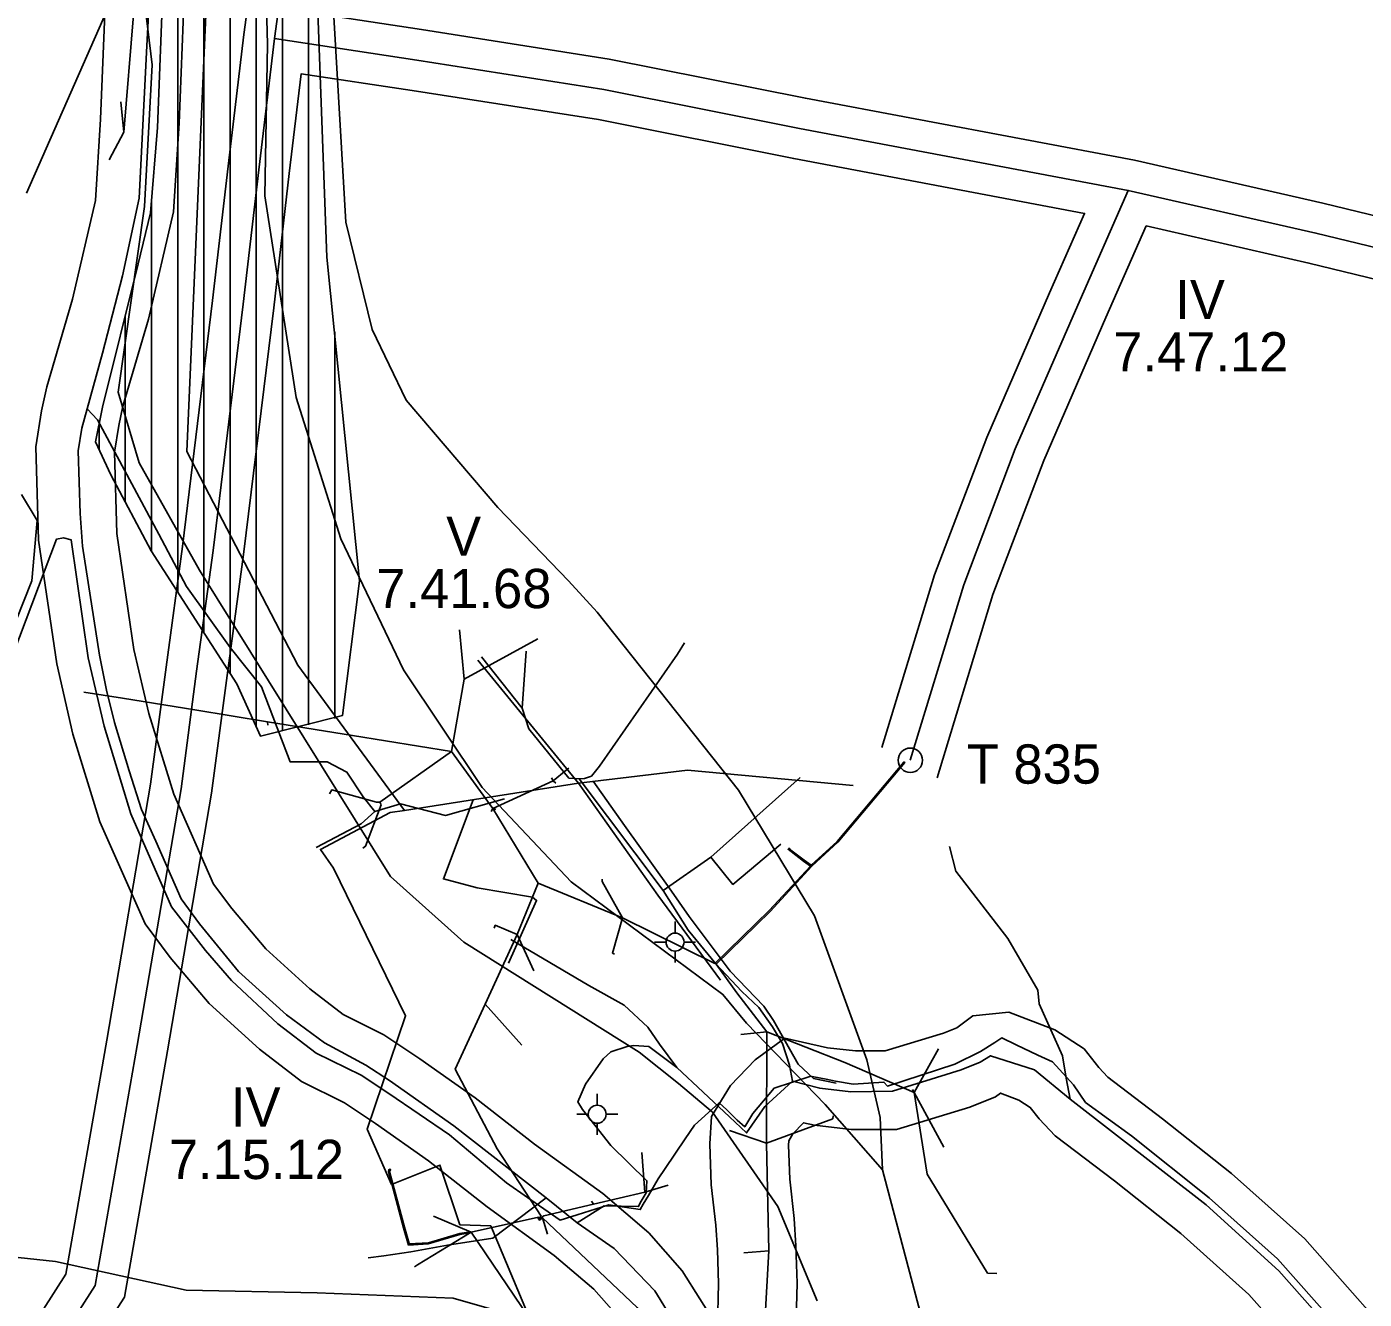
# Model space of a CAD drawing. Extents: x -694504 to -690518, y -983661 to -978958.
# Drawn here: x -693779 to -693268, y -981518 to -981032 of the extents above; entities that cross this region are included whole.
import ezdxf

# ---------------------------------------------------------------- set-up
doc = ezdxf.new("R2010")
doc.units = 0
for name, color, linetype in [('BPEJ', 7, 'Continuous'), ('kabelové a venkovní rozvody telefonu', 7, 'Continuous'), ('ochranné pásmo silnic', 7, 'Continuous'), ('ochranné pásmo vedení', 7, 'Continuous'), ('odvodněné pozemky', 7, 'Continuous'), ('PŘÍRODNÍ PARK JEŠTĚD', 7, 'Continuous'), ('trafostanice', 7, 'Continuous'), ('třídy přednosti v ochraně ZP', 7, 'Continuous'), ('vedení NN', 7, 'Continuous'), ('vedení VN 35kV', 7, 'Continuous'), ('vodní zdroj', 7, 'Continuous'), ('vodovodní řad', 7, 'Continuous')]:
    doc.layers.add(name, color=color, linetype=linetype)

msp = doc.modelspace()

# ---------------------------------------------------------------- linework, layer by layer
at = {"layer": 'BPEJ'}
for points in [[(-693425.4, -981570.81), (-693452.4, -981468.81), (-693453.4, -981448.81), (-693458.4, -981426.81), (-693478.4, -981371.81), (-693507.4, -981323.81), (-693561.4, -981255.81), (-693572.4, -981243.81), (-693599.4, -981215.81), (-693634.4, -981174.81), (-693647.4, -981147.81), (-693657.4, -981106.81), (-693667.4, -980936.81), (-693661.4, -980783.81), (-693666.4, -980694.81), (-693663.4, -980641.81), (-693655.4, -980597.81), (-693644.4, -980565.81)], [(-693800.4, -980663.81), (-693775.4, -980683.81), (-693748.4, -980693.81), (-693748.4, -980693.81), (-693734.4, -980739.81), (-693721.4, -980817.81), (-693722.4, -980839.81), (-693725.4, -980939.81), (-693728.4, -980966.81), (-693736.4, -981005.81), (-693739.4, -981004.81), (-693779.4, -981095.81)], [(-693667.4, -980936.81), (-693657.4, -981106.81), (-693647.4, -981147.81), (-693634.4, -981174.81), (-693599.4, -981215.81), (-693572.4, -981243.81), (-693561.4, -981255.81), (-693507.4, -981323.81), (-693478.4, -981371.81), (-693458.4, -981426.81), (-693453.4, -981448.81), (-693452.4, -981468.81), (-693474.4, -981443.81), (-693504.4, -981412.81), (-693513.4, -981401.81), (-693571.4, -981358.81), (-693605.4, -981322.81), (-693635.4, -981277.81), (-693659.4, -981227.81), (-693676.4, -981173.81), (-693688.4, -981096.81), (-693687.4, -981038.81), (-693688.4, -981000.81)], [(-693779.4, -981095.81), (-693739.4, -981004.81), (-693736.4, -981005.81), (-693736.4, -981005.81), (-693731.4, -981046.81), (-693734.4, -981100.81), (-693744.4, -981171.81), (-693736.4, -981198.81), (-693713.4, -981239.81), (-693640.4, -981356.81), (-693612.4, -981381.81), (-693545.4, -981423.81), (-693530.4, -981435.81), (-693517.4, -981446.81), (-693492.4, -981482.81), (-693477.4, -981518.81)], [(-693795.4, -981288.81), (-693777.4, -981243.81), (-693775.4, -981220.81), (-693781.4, -981210.81)], [(-693588.4, -981525.81), (-693616.4, -981517.81), (-693668.4, -981515.81), (-693718.4, -981514.81), (-693768.4, -981503.81), (-693824.4, -981497.81)]]:
    msp.add_lwpolyline(points, dxfattribs=at)
at = {"layer": 'kabelové a venkovní rozvody telefonu'}
for points in [[(-693527.11, -981535.19), (-693539.39, -981515.06), (-693554.97, -981498.88), (-693569.07, -981489), (-693580.91, -981479.51), (-693616.14, -981451.98), (-693640.75, -981434.69), (-693649.85, -981428.81), (-693665.65, -981420.32), (-693680.09, -981409.66), (-693698.5, -981393), (-693713.4, -981374.88), (-693720.39, -981365.26), (-693730.03, -981343.33), (-693735.52, -981331.16), (-693740.27, -981316.38), (-693745.87, -981297.92), (-693748.85, -981285.66), (-693751.57, -981272.19), (-693758.01, -981230.61), (-693758.87, -981218.17), (-693759.75, -981194.2), (-693758.3, -981185.49), (-693756.27, -981178.12), (-693750.41, -981156.92), (-693742.8, -981127.31), (-693736.34, -981097.67), (-693733.44, -981039.51), (-693732.24, -981015.49)], [(-693756.27, -981178.12), (-693752.34, -981182.35), (-693728.88, -981226.07), (-693718.35, -981245.96), (-693701.69, -981269.36), (-693689.64, -981284.35), (-693678.73, -981312.97), (-693664.6, -981312.97), (-693657.06, -981316.9), (-693650.85, -981326.36), (-693646.39, -981331.94), (-693636.62, -981329.07), (-693619.34, -981333.46), (-693596.81, -981327.09)], [(-693588.61, -981270.77), (-693590.08, -981292.45), (-693587.59, -981300.35), (-693572.22, -981319.23), (-693568.31, -981319.46), (-693566.29, -981319.33), (-693563.62, -981318.49), (-693560.54, -981314.57), (-693530.71, -981271.89), (-693528.08, -981267.51)], [(-693590.08, -981292.45), (-693605.6, -981272.82)], [(-693568.31, -981319.46), (-693536.2, -981362.18), (-693526.62, -981377.22), (-693516.08, -981390.11), (-693506.13, -981400.66), (-693499.68, -981406.81), (-693494.41, -981414.14), (-693490.61, -981420.58), (-693487.97, -981428.79), (-693486.78, -981434.9)], [(-693536.2, -981362.18), (-693518.04, -981349.44), (-693483.9, -981318.98)], [(-693646.39, -981331.94), (-693651.6, -981336.62), (-693668.73, -981345.7)], [(-693518.04, -981349.44), (-693509.56, -981359.78), (-693491.22, -981344.47)], [(-693380.72, -981441.81), (-693382.29, -981433.83), (-693383.75, -981425.33), (-693392.54, -981405.41), (-693393.12, -981400.13), (-693404.54, -981380.5), (-693424.45, -981354.72), (-693426.8, -981345.34)], [(-693594.38, -981380.9), (-693564.64, -981398.42), (-693551.1, -981405.94), (-693542.08, -981414.29), (-693537.57, -981420.85), (-693531.01, -981429.74), (-693510.94, -981448.57), (-693504.38, -981454.73), (-693497.44, -981444.57), (-693486.78, -981434.9), (-693476.42, -981437.63), (-693464.49, -981439.08), (-693448.64, -981438.79), (-693437.58, -981435.3), (-693422.37, -981430.61), (-693415.12, -981427.71), (-693411.14, -981425.27), (-693394.43, -981430.64), (-693380.72, -981441.81), (-693328.86, -981482.12), (-693301.01, -981507.35), (-693274.33, -981537.56)], [(-693531.01, -981429.74), (-693541.7, -981421.76), (-693547.44, -981421.35), (-693550.04, -981421.76), (-693556.18, -981423.76), (-693559.1, -981426.4), (-693565.84, -981436.07), (-693568.77, -981442.81), (-693567.01, -981445.74), (-693556.18, -981459.51), (-693542.41, -981472.98), (-693542.71, -981477.58), (-693545.06, -981481.38), (-693545.64, -981482.85), (-693558.82, -981482.56), (-693569.07, -981489)], [(-693580.91, -981479.51), (-693601.32, -981494.91), (-693618.6, -981497.55), (-693632.66, -981500.19), (-693642.9, -981501.65), (-693648.97, -981502.37)]]:
    msp.add_lwpolyline(points, dxfattribs=at)
at = {"layer": 'ochranné pásmo silnic'}
for points in [[(-693748.77, -981008.39), (-693751.11, -981067.51), (-693753.08, -981098.56), (-693761.85, -981136.24), (-693771.68, -981169.72), (-693773.68, -981178.89), (-693775.91, -981192.7), (-693774.81, -981228.37), (-693767.89, -981275.58), (-693761.7, -981302.35), (-693751.36, -981335.93), (-693734.08, -981374.87), (-693724.56, -981387.67), (-693709.7, -981405.28), (-693690.46, -981422.73), (-693674.4, -981435.06), (-693657.97, -981443.28), (-693646.14, -981451.17), (-693625.86, -981465.4), (-693603.4, -981482.99), (-693577.87, -981501.49), (-693562.77, -981514.33), (-693553.08, -981525.36)], [(-693262.39, -981527.7), (-693291.18, -981495.2), (-693319.1, -981470.22), (-693345.46, -981449.37), (-693366.39, -981433.39), (-693369.82, -981429.77), (-693375.43, -981422.56), (-693386.61, -981415.3), (-693404.21, -981408.54), (-693417.89, -981409.99), (-693424.07, -981414.54), (-693429.18, -981416.65), (-693451.48, -981423.4), (-693462.71, -981423.4), (-693473.45, -981422.17), (-693489.74, -981418.55), (-693501.03, -981426.79), (-693510.57, -981436.66), (-693517.73, -981448.46), (-693518.4, -981458.94), (-693517.84, -981474.55), (-693516.14, -981489.97), (-693515.53, -981499.35), (-693515.04, -981512.19), (-693515.51, -981528.8), (-693528.95, -981507.37), (-693541.68, -981492.89), (-693559.32, -981477.89), (-693585.34, -981459.02), (-693607.98, -981441.3), (-693629.2, -981426.41), (-693642.88, -981417.28), (-693658.41, -981409.52), (-693671.22, -981399.68), (-693688.06, -981384.4), (-693701.04, -981369.02), (-693708.02, -981359.65), (-693723.21, -981325.39), (-693732.72, -981294.54), (-693738.39, -981270.02), (-693744.87, -981225.73), (-693745.83, -981194.64), (-693744.2, -981184.48), (-693742.59, -981177.16), (-693732.83, -981143.88), (-693723.3, -981102.94), (-693721.15, -981069.05), (-693718.85, -981010.9)], [(-693485.69, -981535.32), (-693485.03, -981512.04), (-693485.57, -981497.81), (-693486.25, -981487.35), (-693487.9, -981472.36), (-693488.37, -981459.36), (-693488.26, -981457.73), (-693486.67, -981455.09), (-693482.58, -981450.86), (-693478.42, -981451.8), (-693464.42, -981453.4), (-693447.04, -981453.4), (-693419.08, -981444.94), (-693409.23, -981440.87), (-693407.33, -981439.47), (-693400.31, -981442.17), (-693396.01, -981444.96), (-693392.6, -981449.35), (-693386.5, -981455.78), (-693363.87, -981473.05), (-693338.43, -981493.18), (-693312.48, -981516.4), (-693285.34, -981547.04)]]:
    msp.add_lwpolyline(points, dxfattribs=at)
at = {"layer": 'ochranné pásmo vedení'}
for points in [[(-693651.38, -980679.68), (-693656.92, -980718.26), (-693667.62, -980824.29), (-693683.91, -980933.2), (-693690.14, -980989.43), (-693696.37, -981035.22), (-693702.38, -981085.52), (-693708.34, -981136.78), (-693719.79, -981230.73), (-693726.09, -981276.83), (-693732.01, -981321.47), (-693748.76, -981419.32), (-693764.35, -981508.69), (-693803.41, -981569.49), (-693844.21, -981633.2), (-693885.67, -981697.92), (-693913.63, -981741.57), (-693930.34, -981735.73), (-694180.58, -981650.28), (-694223.83, -981635.39)], [(-692739.96, -981204.97), (-692834.02, -981187.35), (-692924.48, -981170.45), (-693008.63, -981155.22), (-693098.05, -981139.02), (-693191.42, -981122.13), (-693284.2, -981099.61), (-693356.17, -981083.19), (-693481.9, -981059.5), (-693556.87, -981044.56), (-693628.51, -981033.31), (-693671.51, -981026.82), (-693666.81, -980992.3), (-693660.61, -980936.24), (-693644.3, -980827.21), (-693633.59, -980721.11), (-693628.19, -980683.5)], [(-693420.22, -981887.65), (-693499.86, -981883.89), (-693723.37, -981808.05), (-693890.83, -981749.54), (-693865.88, -981710.6), (-693824.42, -981645.88), (-693783.63, -981582.18), (-693742.01, -981517.41), (-693725.61, -981423.32), (-693708.77, -981325), (-693702.8, -981279.97), (-693696.48, -981233.74), (-693685, -981139.56), (-693679.04, -981088.27), (-693674.48, -981050.14), (-693632.09, -981056.54), (-693560.99, -981067.7), (-693486.37, -981082.57), (-693375.28, -981103.51), (-693388.61, -981133.83), (-693412.65, -981189.04), (-693432.57, -981241.52), (-693452.64, -981307.55)], [(-693431.59, -981319.12), (-693410.32, -981249.12), (-693390.88, -981197.91), (-693367.08, -981143.25), (-693351.72, -981108.31), (-693289.59, -981122.49), (-693196.29, -981145.13), (-693102.23, -981162.14), (-693012.81, -981178.34), (-692928.73, -981193.56), (-692838.35, -981210.45), (-692744.28, -981228.07)]]:
    msp.add_lwpolyline(points, dxfattribs=at)
at = {"layer": 'odvodněné pozemky'}
for p, q in [((-693711.68, -981263.65), (-693711.68, -980874.73)), ((-693701.68, -981279.21), (-693701.68, -980876.11)), ((-693691.68, -981299.58), (-693691.68, -980877.48)), ((-693681.68, -981301.17), (-693681.68, -980878.85)), ((-693671.68, -981298.81), (-693671.68, -980880.23)), ((-693721.68, -981248.09), (-693721.68, -980977.08)), ((-693731.68, -981232.52), (-693731.68, -981099.28)), ((-693741.68, -981213.71), (-693741.68, -981142.56)), ((-693661.68, -981296.44), (-693661.68, -981148.74)), ((-693751.68, -981193.68), (-693751.68, -981183.83))]:
    msp.add_line(p, q, dxfattribs=at)
for points in [[(-693753.06, -981190.72), (-693750.43, -981177.55), (-693736.74, -981122.79), (-693732.01, -981103.3), (-693729.37, -981070.66), (-693727.27, -981014.53), (-693720.43, -980968.71), (-693723.07, -980873.17), (-693669.39, -980880.54), (-693659.93, -980881.41), (-693660.98, -980945.13), (-693664.67, -980987.78), (-693668.35, -981019.38), (-693664.7, -981120.28)], [(-693664.7, -981120.28), (-693652.18, -981243.88), (-693658.7, -981295.27), (-693690.06, -981303.15), (-693699.12, -981283.2), (-693731.76, -981232.4), (-693747.17, -981203.37), (-693753.06, -981190.72)]]:
    msp.add_lwpolyline(points, dxfattribs=at)
at = {"layer": 'PŘÍRODNÍ PARK JEŠTĚD'}
msp.add_lwpolyline([(-693784.24, -981271.1), (-693768.03, -981227.94), (-693765.24, -981227.43), (-693762.35, -981228.2), (-693755.85, -981273.23), (-693749.81, -981299.31), (-693739.52, -981332.86), (-693724.09, -981368.35), (-693711.02, -981385), (-693701.14, -981396.48), (-693683.44, -981413), (-693668.83, -981424.19), (-693651.62, -981432.71), (-693641.05, -981439.6), (-693617.9, -981455.5), (-693596.05, -981473.83), (-693588.07, -981479.39), (-693575.61, -981488.07), (-693569.03, -981485.97), (-693566.65, -981485.26), (-693556.96, -981482.18), (-693544.99, -981484), (-693543.81, -981481.97), (-693541.89, -981478.67), (-693538.17, -981472.28), (-693535.51, -981468.34), (-693527.81, -981456.98), (-693524.3, -981451.8), (-693514.9, -981443.2), (-693511.88, -981445.94), (-693508, -981449.89), (-693505.05, -981452.36), (-693503.14, -981449.17), (-693501.94, -981447.35), (-693493.89, -981437.58), (-693479.86, -981433.02), (-693478.68, -981433.26), (-693473.92, -981434.21), (-693470.4, -981434.91), (-693463.59, -981436.12), (-693451.92, -981435.27), (-693450.48, -981436.83), (-693424.8, -981428.41), (-693415.01, -981423.66), (-693409.58, -981420.17), (-693406.91, -981418.46), (-693401.38, -981421.08), (-693393.1, -981425), (-693387.55, -981427.62), (-693379.51, -981436.29), (-693374.96, -981443.04), (-693357.38, -981455.88), (-693327.68, -981479.53), (-693301.58, -981502.83), (-693271.45, -981536.72)], dxfattribs=at)
at = {"layer": 'trafostanice'}
msp.add_ellipse((-693441.83, -981312.38), major_axis=(0, 4.66), ratio=0.997816, dxfattribs=at)
at = {"layer": 'vedení NN'}
for points in [[(-693738.54, -981027.71), (-693742.2, -981072.5)], [(-693742.2, -981072.5), (-693743.42, -981060.86)], [(-693742.2, -981072.5), (-693747.9, -981082.99)], [(-693612.28, -981281.35), (-693614.05, -981262.52)], [(-693612.28, -981281.35), (-693584.11, -981266.04)], [(-693617.12, -981309.07), (-693612.28, -981281.35)], [(-693687.36, -981297.67), (-693715.07, -981293.18), (-693742.73, -981288.69), (-693757.56, -981286.41)], [(-693687.36, -981297.67), (-693687.22, -981298.93)], [(-693617.12, -981309.07), (-693654.92, -981302.94), (-693687.36, -981297.67)], [(-693617.12, -981309.07), (-693644.52, -981328.32)], [(-693601.32, -981330.74), (-693617.12, -981309.07)], [(-693573.29, -981316.22), (-693572.27, -981315.46)], [(-693516.01, -981390.26), (-693495.4, -981370.09), (-693479.47, -981352.85), (-693469.46, -981343.68), (-693443.94, -981313.23), (-693444.13, -981313.15)], [(-693487.94, -981346.06), (-693487.82, -981346.16), (-693487.97, -981346.3), (-693482.42, -981350.54), (-693479.68, -981352.49), (-693469.77, -981343.42), (-693444.33, -981313.06), (-693444.13, -981313.15)], [(-693601.32, -981330.74), (-693578.19, -981320.2)], [(-693578.19, -981320.2), (-693578.84, -981319.15)], [(-693578.19, -981320.2), (-693573.29, -981316.22)], [(-693578.19, -981320.2), (-693577.24, -981321.11)], [(-693645.71, -981328.32), (-693662.84, -981323.71), (-693663.69, -981325.16)], [(-693643.9, -981329.46), (-693649.92, -981345.21), (-693650.89, -981345.9)], [(-693644.52, -981328.32), (-693645.71, -981328.32)], [(-693644.52, -981328.32), (-693643.9, -981329.46)], [(-693601.32, -981330.74), (-693601.91, -981331.89)], [(-693583.96, -981359.27), (-693601.32, -981330.74)], [(-693601.32, -981330.74), (-693600.13, -981331.22)], [(-693516.46, -981389.99), (-693495.68, -981369.81), (-693479.97, -981352.78), (-693482.65, -981350.87), (-693488.51, -981346.34), (-693488.11, -981345.9), (-693487.94, -981346.06)], [(-693583.96, -981359.27), (-693592.01, -981378.92)], [(-693551.8, -981372.53), (-693583.96, -981359.27)], [(-693551.8, -981372.53), (-693559.59, -981358.7), (-693559.47, -981357.74)], [(-693592.01, -981378.92), (-693600.34, -981375.4), (-693600.75, -981376.48)], [(-693551.8, -981372.53), (-693555.6, -981386.1), (-693554.82, -981386.42)], [(-693516.46, -981389.99), (-693551.8, -981372.53)], [(-693592.01, -981378.92), (-693604.23, -981405.55)], [(-693592.01, -981378.92), (-693585.6, -981392.84)], [(-693496.61, -981416.05), (-693508.08, -981401.18), (-693516.01, -981390.26)], [(-693604.23, -981405.55), (-693615.74, -981430.39), (-693599.7, -981460.82), (-693582.89, -981486.57)], [(-693604.23, -981405.55), (-693590.24, -981421.24)], [(-693496.61, -981416.05), (-693506.53, -981417.06)], [(-693496.73, -981458.57), (-693496.61, -981416.05)], [(-693496.61, -981416.05), (-693466.8, -981427.86), (-693440.36, -981439.3)], [(-693440.36, -981439.3), (-693431.05, -981422.56)], [(-693440.36, -981439.3), (-693440.94, -981438.18)], [(-693440.36, -981439.3), (-693435.39, -981470.51), (-693412.29, -981508.33)], [(-693440.36, -981439.3), (-693429.02, -981460.2)], [(-693496.73, -981458.57), (-693471.47, -981449.31), (-693471.35, -981448.2)], [(-693496.73, -981458.57), (-693510.88, -981453.73)], [(-693495.9, -981499.8), (-693496.73, -981458.57)], [(-693543.28, -981477.29), (-693544.4, -981462.13)], [(-693610.76, -981492.79), (-693610.75, -981492.99), (-693613.87, -981493.52), (-693625.94, -981497.11), (-693633.48, -981497.53), (-693635.41, -981490.99), (-693639.35, -981476.13), (-693641.13, -981469.45), (-693641.03, -981468.76), (-693640.5, -981468.52), (-693640.41, -981468.7)], [(-693610.76, -981492.79), (-693610.77, -981492.59), (-693613.94, -981493.12), (-693625.88, -981496.67), (-693633.27, -981497.12), (-693633.23, -981497), (-693635.06, -981490.74), (-693638.97, -981476.02), (-693640.72, -981469.42), (-693640.66, -981469.03), (-693640.33, -981468.88), (-693640.41, -981468.7)], [(-693562.82, -981481.89), (-693543.28, -981477.29)], [(-693543.28, -981477.29), (-693534.26, -981474.65)], [(-693581.83, -981486.42), (-693562.82, -981481.89)], [(-693562.82, -981481.89), (-693563.57, -981480.8)], [(-693609.51, -981492.65), (-693624, -981486.49)], [(-693583.89, -981486.9), (-693609.51, -981492.65)], [(-693583.79, -981487.56), (-693584.13, -981487.07), (-693583.89, -981486.9)], [(-693583.79, -981487.56), (-693583.9, -981487.39), (-693582.89, -981486.57)], [(-693583.79, -981487.56), (-693583.67, -981487.72), (-693581.83, -981486.42)], [(-693583.79, -981487.56), (-693583.44, -981488.05), (-693582.26, -981487.21)], [(-693582.26, -981487.21), (-693580.37, -981493.33)], [(-693582.26, -981487.21), (-693546.21, -981521.35), (-693528.26, -981554.33)], [(-693609.51, -981492.65), (-693630.07, -981505.12), (-693631.26, -981505.91)], [(-693609.51, -981492.65), (-693610.76, -981492.79)], [(-693609.51, -981492.65), (-693587.68, -981524.93)], [(-693528.26, -981554.33), (-693498.22, -981540.56), (-693495.9, -981499.8)], [(-693495.9, -981499.8), (-693505.47, -981500.56)], [(-693412.29, -981508.33), (-693408.75, -981508.46)]]:
    msp.add_lwpolyline(points, dxfattribs=at)
at = {"layer": 'vedení VN 35kV'}
for points in [[(-694329.39, -982435.38), (-694307.8, -982344.86), (-694238.38, -982244.76), (-694180.67, -982160.33), (-694116.67, -982065.53), (-694056.9, -981976.86), (-693977.95, -981861.54), (-693915.76, -981766.68), (-693875.77, -981704.26), (-693834.32, -981639.54), (-693793.52, -981575.83), (-693753.18, -981513.05), (-693737.18, -981421.32), (-693720.39, -981323.23), (-693714.44, -981278.4), (-693708.14, -981232.24), (-693696.67, -981138.17), (-693690.71, -981086.89), (-693684.71, -981036.71), (-693678.48, -980990.86), (-693672.26, -980934.72), (-693655.96, -980825.75), (-693645.25, -980719.68), (-693639.46, -980679.34)], [(-693684.71, -981036.71), (-693630.3, -981044.93), (-693558.93, -981056.13), (-693484.13, -981071.04), (-693358.57, -981094.7), (-693286.9, -981111.05), (-693193.86, -981133.63), (-693100.14, -981150.58), (-693010.72, -981166.78), (-692926.61, -981182), (-692836.19, -981198.9), (-692742.12, -981216.52)], [(-693441.83, -981312.38), (-693421.44, -981245.32), (-693401.76, -981193.48), (-693377.84, -981138.54), (-693358.57, -981094.7)]]:
    msp.add_lwpolyline(points, dxfattribs=at)
at = {"layer": 'vodní zdroj'}
for p, q in [((-693531.7, -981378.41), (-693531.7, -981374.01)), ((-693539.53, -981381.84), (-693535.13, -981381.84)), ((-693528.26, -981381.84), (-693523.86, -981381.84)), ((-693531.7, -981389.67), (-693531.7, -981385.27)), ((-693561.43, -981444.16), (-693561.43, -981439.76)), ((-693569.26, -981447.59), (-693564.86, -981447.59)), ((-693558, -981447.59), (-693553.6, -981447.59)), ((-693561.43, -981455.42), (-693561.43, -981451.02))]:
    msp.add_line(p, q, dxfattribs=at)
for centre in [(-693531.7, -981381.84), (-693561.43, -981447.59)]:
    msp.add_circle(centre, 3.43, dxfattribs=at)
at = {"layer": 'vodovodní řad'}
msp.add_line((-693568.57, -981321.09), (-693607.01, -981274.15), dxfattribs=at)
for points in [[(-693661.76, -980668.83), (-693737.77, -980703.2), (-693726.34, -980744.78), (-693722.18, -980794.68), (-693719.58, -980853.41), (-693704.2, -980872.35), (-693718.24, -981194.42), (-693675.78, -981276.1), (-693635.08, -981331.54), (-693568.57, -981321.09), (-693526.95, -981316.12), (-693463.62, -981321.99)], [(-693568.57, -981321.09), (-693538.32, -981363.93), (-693514.37, -981396.43)], [(-693562.93, -981320.41), (-693551.05, -981337.31), (-693533.92, -981361.16), (-693526.36, -981372.05), (-693510.61, -981392.95), (-693497.75, -981406.35), (-693494.13, -981411.78), (-693484.63, -981428.5), (-693478.75, -981433.93), (-693470.16, -981435.73)], [(-693608.84, -981327.43), (-693620.18, -981357.7), (-693607.26, -981361.16), (-693586.15, -981364.63), (-693584.58, -981365.89), (-693595.29, -981389.85)], [(-693635.08, -981331.54), (-693640.49, -981332.39), (-693667.17, -981346.4), (-693662.2, -981353.64), (-693634.6, -981410.01), (-693649.25, -981453.29), (-693639.99, -981474.4), (-693621.48, -981466.99), (-693613.84, -981489.77), (-693602.08, -981490.22), (-693573.81, -981557.57), (-693543.28, -981563), (-693530.39, -981563), (-693515.46, -981565.71), (-693504.61, -981584.69)]]:
    msp.add_lwpolyline(points, dxfattribs=at)

# ---------------------------------------------------------------- texts
at = {"layer": 'trafostanice'}
msp.add_text('T 835', height=15, dxfattribs=at).set_placement((-693420.27, -981321.32))
at = {"layer": 'třídy přednosti v ochraně ZP'}
for s, p in [('IV', (-693340.61, -981143.89)), ('7.47.12', (-693364.33, -981163.89)), ('V', (-693619.13, -981234.28)), ('7.41.68', (-693645.82, -981254.28)), ('IV', (-693701.34, -981452.33)), ('7.15.12', (-693725.06, -981472.33))]:
    msp.add_text(s, height=15, dxfattribs=at).set_placement(p)

doc.saveas('drawing.dxf')
